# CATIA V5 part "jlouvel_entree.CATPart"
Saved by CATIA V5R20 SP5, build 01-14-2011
Part number: Pièce 1_entrée
Publications: "Longueur_bielle_entree.1"
Bounding box of the stored display mesh (mm): x 0 to 10, y -63 to 7, z -5 to 5
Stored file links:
  E:\IAO_2010\iao\IAO_MMS_Groupe2\IAO_MMS_Groupe2\OK\jlouvel\jlouvel_iao\pièces cao catia ifma\jlouvel_entree.CATPart
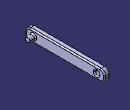
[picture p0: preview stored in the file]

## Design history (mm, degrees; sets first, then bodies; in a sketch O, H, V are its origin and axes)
Parameters
  Longueur_bielle_entree.1 = 70 mm
Body1 (main body)
  Sketch1 on yz-plane, origin (0, 0, 0), H (0, 1, 0), V (0, 0, 1)
    line L1 (7, -5) -> (-63, -5)
    line L2 (-63, -5) -> (-63, 5)
    line L3 (-63, 5) -> (7, 5)
    line L4 (7, 5) -> (7, -5)
    length L4 = 10
    length L3 = 70 {= Longueur_bielle_entree.1}
    distance O L4 = 7
    horizontal: L1 H, L3 H
    vertical: L2 V, L4 V
    symmetry: L1 L3 H
  Pad1: profile Sketch1, direction (1, 0, 0), length 5
  Sketch2 on end face of Pad1, origin (5, 0, 0), H (0, 1, 0), V (0, 0, 1)
    circle A1 centre (0, 0) radius 2
    radius A1 = 2
  Pocket1: profile Sketch2, direction (-1, 0, 0), through (limit type 6)
  Sketch3 on end face of Pad1, origin (5, 0, 0), H (0, 1, 0), V (0, 0, 1)
    circle A1 centre (-56, 0) radius 2
    point P1 (-56, 0)
    reference projected line E1 (-63, 5) -> (-63, -5) from edge [face of Pad1 from Sketch1.L2 | end face of Pad1]
    radius A1 = 2
    distance P1 H = 0
    distance P1 E1 = 7
  Pad2: profile Sketch3, direction (1, 0, 0), length 5
  Fillet1: radius 4, on edge [face of Pad1 from Sketch1.L3 | face of Pad1 from Sketch1.L4]; edge [face of Pad1 from Sketch1.L4 | face of Pad1 from Sketch1.L1]; edge [face of Pad1 from Sketch1.L2 | face of Pad1 from Sketch1.L3]; edge [face of Pad1 from Sketch1.L1 | face of Pad1 from Sketch1.L2]
  Fillet2: radius 1, on end face of Pad1; start face of Pad1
